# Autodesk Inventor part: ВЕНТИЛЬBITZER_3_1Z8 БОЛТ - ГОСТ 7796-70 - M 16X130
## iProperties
Created: 2011-02
Part Number: ВЕНТИЛЬBITZER_3_1Z8 БОЛТ - ГОСТ 7796-70 - M 16X130
Document SubType Name: Modeling
Designer: Чернышев Юрий
Mass: 29.7779 g
Surface Area: 80.3169 cm^2
Volume: 29.7779 cm^3
Density: 1 g/cm^3
Author: Чернышев Юрий
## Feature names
1. Base1
